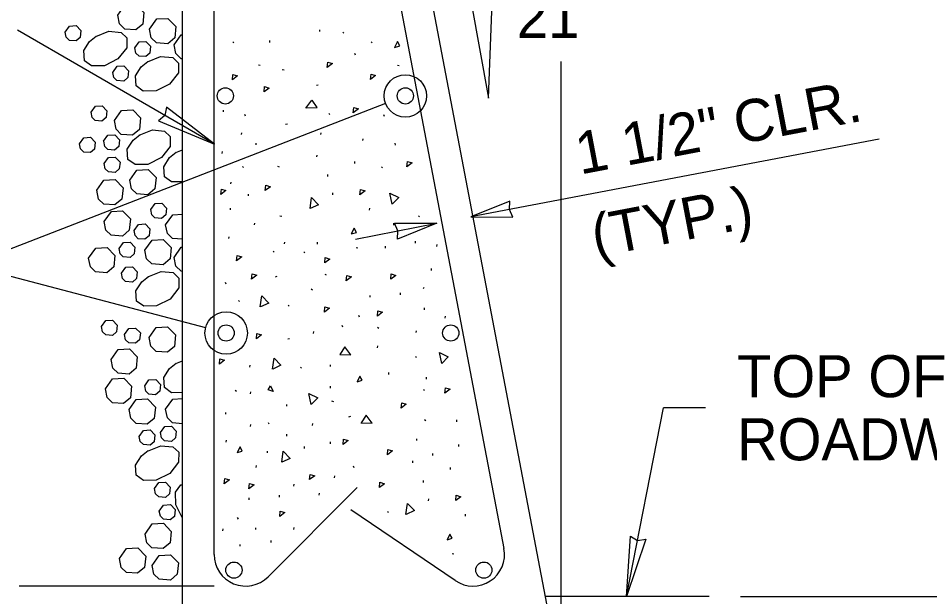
# Model space of a CAD drawing. Extents: x 99862 to 103680, y 99470 to 102076.
# Drawn here: x 102331.5 to 102678.1, y 101103.5 to 101323.5 of the extents above; entities that cross this region are included whole.
import ezdxf

# ---------------------------------------------------------------- set-up
doc = ezdxf.new("R2010")
doc.units = 0
for name, color, linetype in [('Level 10', 7, 'Continuous'), ('Level 13', 7, 'Continuous'), ('Level 15', 7, 'Continuous'), ('Level 16', 7, 'Continuous'), ('Level 2', 7, 'Continuous'), ('Level 20', 7, 'Continuous'), ('Level 7', 7, 'Continuous')]:
    doc.layers.add(name, color=color, linetype=linetype)

msp = doc.modelspace()

# ---------------------------------------------------------------- linework, layer by layer
at = {"layer": 'Level 10'}
for p, q in [((102468.99, 101369.72), (102516.21, 101121.79)), ((102406, 101119.55), (102406, 101363.77)), ((102460.42, 101145), (102426.48, 101111.06)), ((102497.67, 101109.62), (102457.98, 101136.61))]:
    msp.add_line(p, q, dxfattribs=at)
for centre in [(102410.24, 101293.99), (102478.71, 101293.99), (102410.56, 101203.81), (102495.96, 101203.81), (102413.51, 101113.63), (102508.55, 101113.63)]:
    msp.add_circle(centre, 3.08, dxfattribs=at)
for centre, start, end in [((102504.42, 101119.55), 235.7843, 10.7843), ((102418, 101119.55), 180, 315)]:
    msp.add_arc(centre, 12, start, end, dxfattribs=at)
at = {"layer": 'Level 13'}
for p, q in [((102446.19, 101318.46), (102446.24, 101319.18)), ((102427.18, 101314.35), (102427.23, 101315.07)), ((102454.91, 101318.28), (102455.33, 101317.96)), ((102413.11, 101314.58), (102413.53, 101314.26)), ((102465.67, 101314.53), (102466.1, 101314.22)), ((102459.35, 101310.21), (102459.64, 101309.61)), ((102423.49, 101305.51), (102422.85, 101305.68)), ((102476.39, 101305.41), (102475.75, 101305.58)), ((102432.56, 101303.74), (102431.87, 101303.93)), ((102444.87, 101298.04), (102445.51, 101298.22)), ((102409.51, 101287.89), (102409.56, 101288.61)), ((102417.5, 101287.02), (102417.8, 101286.43)), ((102449.61, 101287.25), (102450.04, 101286.94)), ((102470.4, 101286.92), (102470.69, 101286.33)), ((102433.19, 101283.2), (102433.89, 101283.39)), ((102416.42, 101279.26), (102416.47, 101279.98)), ((102446.61, 101279.26), (102446.66, 101279.98)), ((102462.57, 101276.99), (102462.62, 101277.71)), ((102422.01, 101275.36), (102421.96, 101276.08)), ((102474.9, 101275.26), (102474.85, 101275.98)), ((102409.1, 101272.07), (102409.15, 101272.79)), ((102445.08, 101270.79), (102445.13, 101271.51)), ((102416.74, 101267.1), (102417.17, 101266.78)), ((102430.86, 101266.9), (102430.16, 101267.09)), ((102459.43, 101268.27), (102459.48, 101268.99)), ((102469.64, 101267), (102470.07, 101266.68)), ((102449.18, 101263.35), (102449.23, 101264.07)), ((102412.36, 101260.5), (102412.41, 101261.22)), ((102419, 101255.96), (102419.05, 101256.68)), ((102451.11, 101256.37), (102451.16, 101257.09)), ((102412.21, 101250.63), (102412.26, 101251.35)), ((102465.11, 101250.53), (102465.16, 101251.25)), ((102431.7, 101248.1), (102431, 101248.29)), ((102483.7, 101248.4), (102484.13, 101248.09)), ((102421.38, 101244.93), (102421.43, 101245.65)), ((102474.28, 101244.83), (102474.33, 101245.55)), ((102411.63, 101239.73), (102411.68, 101240.45)), ((102432.79, 101237.68), (102432.84, 101238.4)), ((102445.3, 101237.65), (102445.34, 101238.37)), ((102460.69, 101236.04), (102460.05, 101236.21)), ((102471.14, 101236.11), (102471.19, 101236.83)), ((102482.51, 101238.04), (102482.55, 101238.76)), ((102490.69, 101236.72), (102490.74, 101237.43)), ((102428.45, 101234.94), (102428.88, 101234.63)), ((102440.05, 101234.63), (102440.47, 101234.32)), ((102429.38, 101225.19), (102430.02, 101225.37)), ((102448.12, 101226.25), (102448.54, 101225.94)), ((102488.59, 101227.59), (102488.64, 101228.31)), ((102410.21, 101223.09), (102410.5, 101222.5)), ((102442.94, 101220.6), (102443.37, 101220.29)), ((102465.32, 101217.39), (102465.37, 101218.11)), ((102476.81, 101218.37), (102476.86, 101219.09)), ((102415.24, 101216.12), (102415.67, 101215.81)), ((102434.12, 101214.4), (102434.55, 101214.09)), ((102485.98, 101212.67), (102486.03, 101213.39)), ((102460.83, 101210.6), (102461.13, 101210.01)), ((102493.9, 101209.5), (102493.94, 101210.22)), ((102443.81, 101203.61), (102443.86, 101204.33)), ((102454.56, 101206.75), (102454.85, 101206.15)), ((102468.14, 101206), (102468.57, 101205.68)), ((102482.84, 101203.95), (102482.89, 101204.67)), ((102434.06, 101201.57), (102434.7, 101201.74)), ((102468.13, 101198.16), (102468.18, 101198.88)), ((102482.55, 101195.03), (102482.85, 101194.44)), ((102419.58, 101190.84), (102419.63, 101191.56)), ((102438.8, 101190.78), (102439.23, 101190.47)), ((102450.19, 101191.03), (102450.24, 101191.75)), ((102472.39, 101188.03), (102472.44, 101188.75)), ((102486.72, 101186.3), (102486.77, 101187.02)), ((102450.19, 101182.83), (102450.24, 101183.55)), ((102414.05, 101182.05), (102414.48, 101181.74)), ((102419.87, 101180.67), (102419.92, 101181.39)), ((102485.56, 101182.49), (102485.85, 101181.9)), ((102433.62, 101175.96), (102433.67, 101176.68)), ((102451.46, 101177.67), (102450.77, 101177.86)), ((102410.38, 101172.91), (102410.43, 101173.63)), ((102426.52, 101169.81), (102426.81, 101169.22)), ((102457.27, 101171.97), (102457.91, 101172.14)), ((102486.04, 101170.89), (102486.47, 101170.58)), ((102498.26, 101170.01), (102498.31, 101170.73)), ((102419.87, 101168.24), (102419.92, 101168.96)), ((102443.44, 101168.61), (102443.49, 101169.33)), ((102410.58, 101162.32), (102410.63, 101163.04)), ((102433.62, 101164.63), (102433.67, 101165.35)), ((102483.04, 101162.9), (102483.09, 101163.62)), ((102440.3, 101159.89), (102440.35, 101160.61)), ((102450.19, 101161.66), (102450.24, 101162.38)), ((102499, 101160.62), (102499.05, 101161.34)), ((102426.28, 101158.2), (102426.33, 101158.92)), ((102489.14, 101157.24), (102489.19, 101157.96)), ((102422.02, 101152.64), (102422.07, 101153.36)), ((102458.84, 101153.27), (102459.14, 101152.68)), ((102481.51, 101154.43), (102481.56, 101155.15)), ((102495.86, 101151.91), (102495.91, 101152.63)), ((102451.79, 101148.75), (102451.84, 101149.47)), ((102436.32, 101145.59), (102436.37, 101146.3)), ((102485.61, 101146.99), (102485.66, 101147.71)), ((102430.79, 101141.36), (102430.84, 101142.08)), ((102445.97, 101142.16), (102446.02, 101142.88)), ((102419.3, 101140.38), (102419.35, 101141.1)), ((102487.54, 101140.01), (102487.59, 101140.73)), ((102471.92, 101136.08), (102472.21, 101135.49)), ((102501.54, 101134.17), (102501.59, 101134.89)), ((102414.81, 101133.59), (102415.11, 101133)), ((102409.33, 101128.57), (102409.38, 101129.29)), ((102421.79, 101129.04), (102421.84, 101129.76)), ((102436.32, 101129.11), (102436.37, 101129.83)), ((102427.63, 101124.16), (102427.68, 101124.88)), ((102415.85, 101122.67), (102415.9, 101123.39)), ((102497.11, 101119.68), (102496.47, 101119.85))]:
    msp.add_line(p, q, dxfattribs=at)
for points in [[(102474.62, 101312.46), (102476.57, 101313.04), (102475.71, 101314.66), (102474.62, 101312.46)], [(102449, 101304.84), (102449.2, 101306.87), (102450.95, 101306.34), (102449, 101304.84)], [(102412.92, 101300.1), (102413.12, 101302.12), (102414.87, 101301.59), (102412.92, 101300.1)], [(102465.45, 101300.22), (102465.65, 101302.24), (102467.41, 101301.71), (102465.45, 101300.22)], [(102425, 101295.5), (102425.19, 101297.53), (102426.95, 101297), (102425, 101295.5)], [(102445.13, 101289.47), (102440.91, 101289.39), (102443.17, 101292.41), (102445.1, 101289.54)], [(102458.92, 101287.59), (102459.12, 101289.61), (102460.87, 101289.08), (102458.92, 101287.59)], [(102479.28, 101267.08), (102479.48, 101269.11), (102481.23, 101268.58), (102479.28, 101267.08)], [(102425.41, 101257.97), (102425.6, 101260), (102427.36, 101259.46), (102425.41, 101257.97)], [(102408.53, 101256.51), (102408.73, 101258.53), (102410.48, 101258), (102408.53, 101256.51)], [(102461.43, 101256.41), (102461.63, 101258.43), (102463.38, 101257.9), (102461.43, 101256.41)], [(102473.74, 101252.87), (102472.86, 101257), (102476.25, 101255.35), (102473.8, 101252.92)], [(102442.49, 101251.13), (102443.07, 101255.31), (102445.7, 101252.61), (102442.56, 101251.15)], [(102458.12, 101241.51), (102460.07, 101242.09), (102459.21, 101243.71), (102458.12, 101241.51)], [(102414.52, 101231.27), (102414.72, 101233.29), (102416.47, 101232.76), (102414.52, 101231.27)], [(102448.06, 101230.47), (102448.26, 101232.49), (102450.02, 101231.96), (102448.06, 101230.47)], [(102420.23, 101224.35), (102420.43, 101226.37), (102422.19, 101225.84), (102420.23, 101224.35)], [(102456.25, 101223.68), (102456.45, 101225.7), (102458.2, 101225.17), (102456.25, 101223.68)], [(102473.13, 101224.25), (102473.33, 101226.27), (102475.08, 101225.74), (102473.13, 101224.25)], [(102485.91, 101221.17), (102485.5, 101220.76)], [(102423.52, 101213.71), (102424.1, 101217.89), (102426.73, 101215.18), (102423.59, 101213.73)], [(102447.93, 101211.77), (102448.13, 101213.8), (102449.88, 101213.26), (102447.93, 101211.77)], [(102468.09, 101210.21), (102468.29, 101212.23), (102470.04, 101211.7), (102468.09, 101210.21)], [(102422.07, 101201.58), (102422.27, 101203.6), (102424.02, 101203.07), (102422.07, 101201.58)], [(102453.75, 101195.6), (102457.98, 101195.52), (102455.71, 101198.53), (102453.79, 101195.66)], [(102407.98, 101191.93), (102408.18, 101193.95), (102409.93, 101193.42), (102407.98, 101191.93)], [(102428.2, 101190.08), (102428.78, 101194.27), (102431.41, 101191.56), (102428.27, 101190.11)], [(102492.52, 101192.22), (102491.64, 101196.35), (102495.03, 101194.7), (102492.58, 101192.26)], [(102460.33, 101185.24), (102462.27, 101185.82), (102461.42, 101187.44), (102460.33, 101185.24)], [(102428.5, 101181.58), (102426.55, 101182.17), (102427.41, 101183.78), (102428.5, 101181.58)], [(102442.9, 101176.65), (102442.02, 101180.78), (102445.41, 101179.14), (102442.96, 101176.7)], [(102493.76, 101180.91), (102493.96, 101182.93), (102495.71, 101182.4), (102493.76, 101180.91)], [(102477.12, 101175.28), (102477.32, 101177.3), (102479.07, 101176.77), (102477.12, 101175.28)], [(102461.83, 101169.62), (102466.06, 101169.54), (102463.79, 101172.56), (102461.87, 101169.69)], [(102455.04, 101161.4), (102455.24, 101163.42), (102456.99, 101162.89), (102455.04, 101161.4)], [(102414.76, 101158.31), (102416.7, 101158.89), (102415.85, 101160.51), (102414.76, 101158.31)], [(102471.86, 101157.52), (102472.06, 101159.54), (102473.82, 101159.01), (102471.86, 101157.52)], [(102431.68, 101154.65), (102432.26, 101158.84), (102434.88, 101156.13), (102431.75, 101154.68)], [(102442.29, 101148.03), (102442.49, 101150.05), (102444.24, 101149.52), (102442.29, 101148.03)], [(102409.81, 101146.48), (102410.01, 101148.5), (102411.77, 101147.97), (102409.81, 101146.48)], [(102419.24, 101144.57), (102419.44, 101146.6), (102421.19, 101146.06), (102419.24, 101144.57)], [(102468.84, 101145.01), (102469.04, 101147.03), (102470.8, 101146.5), (102468.84, 101145.01)], [(102497.85, 101140.04), (102498.05, 101142.07), (102499.81, 101141.53), (102497.85, 101140.04)], [(102478.92, 101134.76), (102479.5, 101138.95), (102482.13, 101136.24), (102478.99, 101134.79)], [(102430.95, 101133.99), (102431.15, 101136.01), (102432.91, 101135.48), (102430.95, 101133.99)], [(102494.55, 101125.14), (102496.5, 101125.72), (102495.64, 101127.34), (102494.55, 101125.14)]]:
    msp.add_lwpolyline(points, dxfattribs=at)
at = {"layer": 'Level 15'}
for p, q in [((102406.16, 101275.7), (102331.25, 101318.94)), ((102538, 101226.2), (102538, 101307.09)), ((102658.85, 101277.56), (102503.58, 101247.99)), ((102459.77, 101239.53), (102490.62, 101245.53)), ((102538, 101084.63), (102538, 101226.2)), ((102562.85, 101103.53), (102576.9, 101175.37)), ((102592.84, 101175.38), (102576.84, 101175.38)), ((102406.01, 101107.55), (102331.84, 101107.55)), ((102606.2, 101103.55), (102764, 101103.55))]:
    msp.add_line(p, q, dxfattribs=at)
for points in [[(102510.38, 101293.13), (102513.09, 101366.08), (102497.09, 101366.08)], [(102406.16, 101275.7), (102387.88, 101289.7), (102387.3, 101286.58), (102384.89, 101284.53)], [(102503.58, 101247.99), (102519.6, 101247.9), (102518.31, 101250.79), (102518.45, 101253.96)], [(102490.62, 101245.53), (102475.77, 101239.5), (102475.9, 101242.67), (102474.59, 101245.55)], [(102562.85, 101103.53), (102564.3, 101126.51), (102567.03, 101124.9), (102570.16, 101125.36)]]:
    msp.add_lwpolyline(points, close=True, dxfattribs=at)
msp.add_lwpolyline([(102471.17, 101291.07), (102312.57, 101229.59), (102402.74, 101205.87)], dxfattribs=at)
for centre in [(102478.71, 101293.99), (102410.56, 101203.81)]:
    msp.add_circle(centre, 8.08, dxfattribs=at)
at = {"layer": 'Level 16'}
msp.add_line((102594.2, 101103.55), (102531.9, 101103.55), dxfattribs=at)
at = {"layer": 'Level 2'}
msp.add_lwpolyline([(102394, 101071.55), (102394, 101401.55), (102400, 101407.55), (102468, 101407.55), (102475.12, 101401.65), (102538, 101071.55)], dxfattribs=at)
at = {"layer": 'Level 7'}
for points in [[(102369.32, 101324.69), (102372.01, 101328.52), (102376.31, 101328.76), (102379.29, 101325.67), (102378.86, 101321.33), (102376.21, 101319.13), (102371.97, 101319.43), (102369.97, 101321.37), (102369.33, 101324.69)], [(102381.46, 101319.42), (102384.15, 101323.25), (102388.44, 101323.49), (102391.43, 101320.4), (102391, 101316.06), (102388.34, 101313.86), (102384.1, 101314.16), (102382.11, 101316.1), (102381.46, 101319.42)], [(102349.35, 101318.28), (102350.96, 101320.57), (102353.54, 101320.72), (102355.33, 101318.86), (102355.07, 101316.26), (102353.48, 101314.94), (102350.93, 101315.12), (102349.74, 101316.28), (102349.35, 101318.28)], [(102360.98, 101316.57), (102366.01, 101318.56), (102370.63, 101318.17), (102372.83, 101316.08), (102372.76, 101312.33), (102369.43, 101308.07), (102364.28, 101305.49), (102359.42, 101305.4), (102356.69, 101307.35), (102356.43, 101311.21), (102358.65, 101314.67), (102361.19, 101316.7)], [(102390.79, 101313.41), (102393.48, 101317.23), (102394, 101317.26)], [(102375.86, 101312.29), (102377.47, 101314.58), (102380.05, 101314.73), (102381.84, 101312.87), (102381.58, 101310.27), (102379.99, 101308.95), (102377.44, 101309.13), (102376.25, 101310.29), (102375.86, 101312.29)], [(102394, 101308.11), (102393.43, 101308.15), (102391.44, 101310.08), (102390.79, 101313.41)], [(102380.6, 101306.99), (102385.63, 101308.98), (102390.25, 101308.59), (102392.45, 101306.5), (102392.38, 101302.75), (102389.05, 101298.49), (102383.9, 101295.91), (102379.04, 101295.83), (102376.31, 101297.77), (102376.05, 101301.63), (102378.27, 101305.09), (102380.81, 101307.12)], [(102367.46, 101302.96), (102369.07, 101305.25), (102371.65, 101305.4), (102373.44, 101303.54), (102373.18, 101300.94), (102371.59, 101299.62), (102369.05, 101299.8), (102367.85, 101300.96), (102367.46, 101302.96)], [(102359.2, 101287.75), (102360.82, 101290.04), (102363.39, 101290.19), (102365.18, 101288.33), (102364.92, 101285.73), (102363.33, 101284.41), (102360.79, 101284.59), (102359.59, 101285.75), (102359.2, 101287.75)], [(102368.05, 101284.64), (102370.74, 101288.47), (102375.03, 101288.72), (102378.01, 101285.62), (102377.58, 101281.28), (102374.93, 101279.08), (102370.69, 101279.38), (102368.7, 101281.32), (102368.05, 101284.64)], [(102377.47, 101279.04), (102382.5, 101281.03), (102387.12, 101280.63), (102389.32, 101278.54), (102389.25, 101274.79), (102385.92, 101270.53), (102380.77, 101267.96), (102375.91, 101267.87), (102373.18, 101269.81), (102372.92, 101273.68), (102375.14, 101277.14), (102377.68, 101279.16)], [(102354.83, 101275.8), (102356.44, 101278.1), (102359.02, 101278.24), (102360.81, 101276.39), (102360.55, 101273.78), (102358.96, 101272.46), (102356.41, 101272.64), (102355.22, 101273.81), (102354.83, 101275.8)], [(102363.98, 101276.74), (102365.6, 101279.04), (102368.17, 101279.18), (102369.96, 101277.33), (102369.71, 101274.72), (102368.11, 101273.4), (102365.57, 101273.58), (102364.37, 101274.74), (102363.99, 101276.74)], [(102391.4, 101272.44), (102394, 101273.47)], [(102364.22, 101268.26), (102365.83, 101270.56), (102368.41, 101270.7), (102370.2, 101268.85), (102369.94, 101266.25), (102368.35, 101264.92), (102365.81, 101265.11), (102364.61, 101266.27), (102364.22, 101268.26)], [(102394, 101261.35), (102389.83, 101261.27), (102387.1, 101263.22), (102386.84, 101267.08), (102389.06, 101270.54), (102391.6, 101272.57)], [(102373.95, 101261.96), (102376.64, 101265.78), (102380.93, 101266.03), (102383.92, 101262.93), (102383.48, 101258.6), (102380.83, 101256.39), (102376.59, 101256.7), (102374.6, 101258.63), (102373.95, 101261.96)], [(102361.37, 101258.08), (102364.06, 101261.9), (102368.35, 101262.15), (102371.34, 101259.06), (102370.91, 101254.72), (102368.25, 101252.51), (102364.02, 101252.82), (102362.02, 101254.75), (102361.37, 101258.08)], [(102381.89, 101250.75), (102383.51, 101253.04), (102386.08, 101253.19), (102387.87, 101251.33), (102387.61, 101248.73), (102386.02, 101247.41), (102383.48, 101247.59), (102382.28, 101248.75), (102381.89, 101250.74)], [(102364.21, 101246.24), (102366.9, 101250.06), (102371.19, 101250.31), (102374.17, 101247.21), (102373.74, 101242.88), (102371.09, 101240.67), (102366.85, 101240.98), (102364.86, 101242.91), (102364.21, 101246.24)], [(102387.56, 101244.99), (102390.25, 101248.82), (102394, 101249.03)], [(102375.56, 101242.84), (102377.18, 101245.13), (102379.75, 101245.28), (102381.54, 101243.42), (102381.28, 101240.82), (102379.69, 101239.5), (102377.15, 101239.68), (102375.95, 101240.84), (102375.56, 101242.84)], [(102394, 101239.46), (102390.2, 101239.73), (102388.21, 101241.67), (102387.56, 101244.99)], [(102379.68, 101235.33), (102382.37, 101239.15), (102386.67, 101239.4), (102389.65, 101236.3), (102389.22, 101231.97), (102386.57, 101229.76), (102382.33, 101230.07), (102380.33, 101232), (102379.69, 101235.33)], [(102358.28, 101232.3), (102360.97, 101236.12), (102365.26, 101236.37), (102368.24, 101233.27), (102367.81, 101228.94), (102365.16, 101226.73), (102360.92, 101227.04), (102358.93, 101228.97), (102358.28, 101232.3)], [(102369.87, 101235.91), (102371.48, 101238.2), (102374.06, 101238.35), (102375.85, 101236.49), (102375.59, 101233.89), (102374, 101232.57), (102371.45, 101232.75), (102370.25, 101233.91), (102369.87, 101235.91)], [(102390.79, 101232.57), (102393.48, 101236.4), (102394, 101236.43)], [(102394, 101227.27), (102393.43, 101227.31), (102391.44, 101229.25), (102390.79, 101232.57)], [(102370.76, 101226.55), (102372.37, 101228.85), (102374.95, 101228.99), (102376.74, 101227.14), (102376.48, 101224.54), (102374.89, 101223.21), (102372.34, 101223.4), (102371.15, 101224.56), (102370.76, 101226.55)], [(102380.78, 101225.2), (102385.82, 101227.19), (102390.44, 101226.79), (102392.63, 101224.71), (102392.56, 101220.96), (102389.23, 101216.69), (102384.08, 101214.12), (102379.22, 101214.03), (102376.49, 101215.98), (102376.23, 101219.84), (102378.45, 101223.3), (102380.99, 101225.33)], [(102363.16, 101206.26), (102364.78, 101208.56), (102367.35, 101208.7), (102369.15, 101206.85), (102368.89, 101204.24), (102367.3, 101202.92), (102364.75, 101203.1), (102363.55, 101204.26), (102363.17, 101206.26)], [(102371.95, 101203.25), (102373.57, 101205.55), (102376.14, 101205.7), (102377.93, 101203.84), (102377.67, 101201.24), (102376.08, 101199.91), (102373.54, 101200.1), (102372.34, 101201.26), (102371.95, 101203.25)], [(102381.33, 101202.08), (102384.01, 101205.91), (102388.31, 101206.15), (102391.29, 101203.06), (102390.86, 101198.72), (102388.21, 101196.52), (102383.97, 101196.82), (102381.98, 101198.76), (102381.33, 101202.08)], [(102366.81, 101193.75), (102369.5, 101197.57), (102373.79, 101197.82), (102376.77, 101194.72), (102376.34, 101190.39), (102373.69, 101188.18), (102369.45, 101188.49), (102367.46, 101190.42), (102366.81, 101193.74)], [(102394, 101181.16), (102389.83, 101181.09), (102387.1, 101183.03), (102386.84, 101186.9), (102389.06, 101190.36), (102391.6, 101192.38)], [(102391.4, 101192.25), (102394, 101193.28)], [(102364.65, 101182.56), (102367.34, 101186.38), (102371.64, 101186.63), (102374.62, 101183.53), (102374.19, 101179.2), (102371.54, 101176.99), (102367.3, 101177.3), (102365.3, 101179.23), (102364.66, 101182.56)], [(102379.6, 101183.67), (102381.22, 101185.97), (102383.79, 101186.12), (102385.58, 101184.26), (102385.32, 101181.66), (102383.73, 101180.33), (102381.19, 101180.52), (102379.99, 101181.68), (102379.6, 101183.67)], [(102373.68, 101174.69), (102376.37, 101178.51), (102380.66, 101178.76), (102383.65, 101175.66), (102383.22, 101171.33), (102380.56, 101169.12), (102376.33, 101169.43), (102374.33, 101171.36), (102373.68, 101174.69)], [(102387.56, 101174.85), (102390.25, 101178.67), (102394, 101178.89)], [(102394, 101169.31), (102390.2, 101169.59), (102388.21, 101171.52), (102387.56, 101174.85)], [(102377.5, 101164.49), (102379.11, 101166.79), (102381.69, 101166.94), (102383.48, 101165.08), (102383.22, 101162.48), (102381.63, 101161.15), (102379.08, 101161.34), (102377.89, 101162.5), (102377.5, 101164.49)], [(102385.59, 101165.93), (102387.2, 101168.23), (102389.78, 101168.37), (102391.57, 101166.52), (102391.31, 101163.91), (102389.72, 101162.59), (102387.17, 101162.78), (102385.98, 101163.94), (102385.59, 101165.93)], [(102380.67, 101158.93), (102385.7, 101160.93), (102390.32, 101160.53), (102392.52, 101158.44), (102392.45, 101154.69), (102389.11, 101150.43), (102383.96, 101147.85), (102379.11, 101147.77), (102376.37, 101149.71), (102376.12, 101153.58), (102378.33, 101157.03), (102380.87, 101159.06)], [(102383.33, 101144.62), (102384.95, 101146.91), (102387.52, 101147.06), (102389.31, 101145.2), (102389.05, 101142.6), (102387.46, 101141.28), (102384.92, 101141.46), (102383.72, 101142.62), (102383.33, 101144.62)], [(102394, 101133.33), (102391.45, 101138.43), (102391.36, 101143.28), (102393.3, 101146.02), (102394, 101146.06)], [(102385.15, 101136.1), (102386.76, 101138.39), (102389.34, 101138.54), (102391.13, 101136.68), (102390.87, 101134.08), (102389.28, 101132.76), (102386.74, 101132.94), (102385.54, 101134.1), (102385.15, 101136.1)], [(102379.71, 101127.36), (102382.4, 101131.18), (102386.7, 101131.43), (102389.68, 101128.33), (102389.25, 101124), (102386.6, 101121.79), (102382.36, 101122.1), (102380.36, 101124.03), (102379.72, 101127.36)], [(102370, 101118.01), (102372.68, 101121.83), (102376.98, 101122.08), (102379.96, 101118.98), (102379.53, 101114.65), (102376.88, 101112.44), (102372.64, 101112.75), (102370.64, 101114.68), (102370, 101118.01)], [(102382.46, 101115.4), (102385.15, 101119.23), (102389.44, 101119.47), (102392.42, 101116.38), (102391.99, 101112.04), (102389.34, 101109.84), (102385.1, 101110.14), (102383.11, 101112.08), (102382.46, 101115.4)]]:
    msp.add_lwpolyline(points, dxfattribs=at)

# ---------------------------------------------------------------- texts
at = {"layer": 'Level 20'}
for s, p in [('21', (102521.11, 101316.08)), ('TOP OF', (102604.84, 101179.38)), ('ROADWAY', (102604.84, 101155.38))]:
    msp.add_text(s, height=16, dxfattribs=at).set_placement(p)
for s, p in [('1 1/2" CLR.', (102545.16, 101264.05)), ('(TYP.)', (102551.15, 101232.62))]:
    msp.add_text(s, height=16, rotation=10.7843, dxfattribs=at).set_placement(p)

doc.saveas('drawing.dxf')
